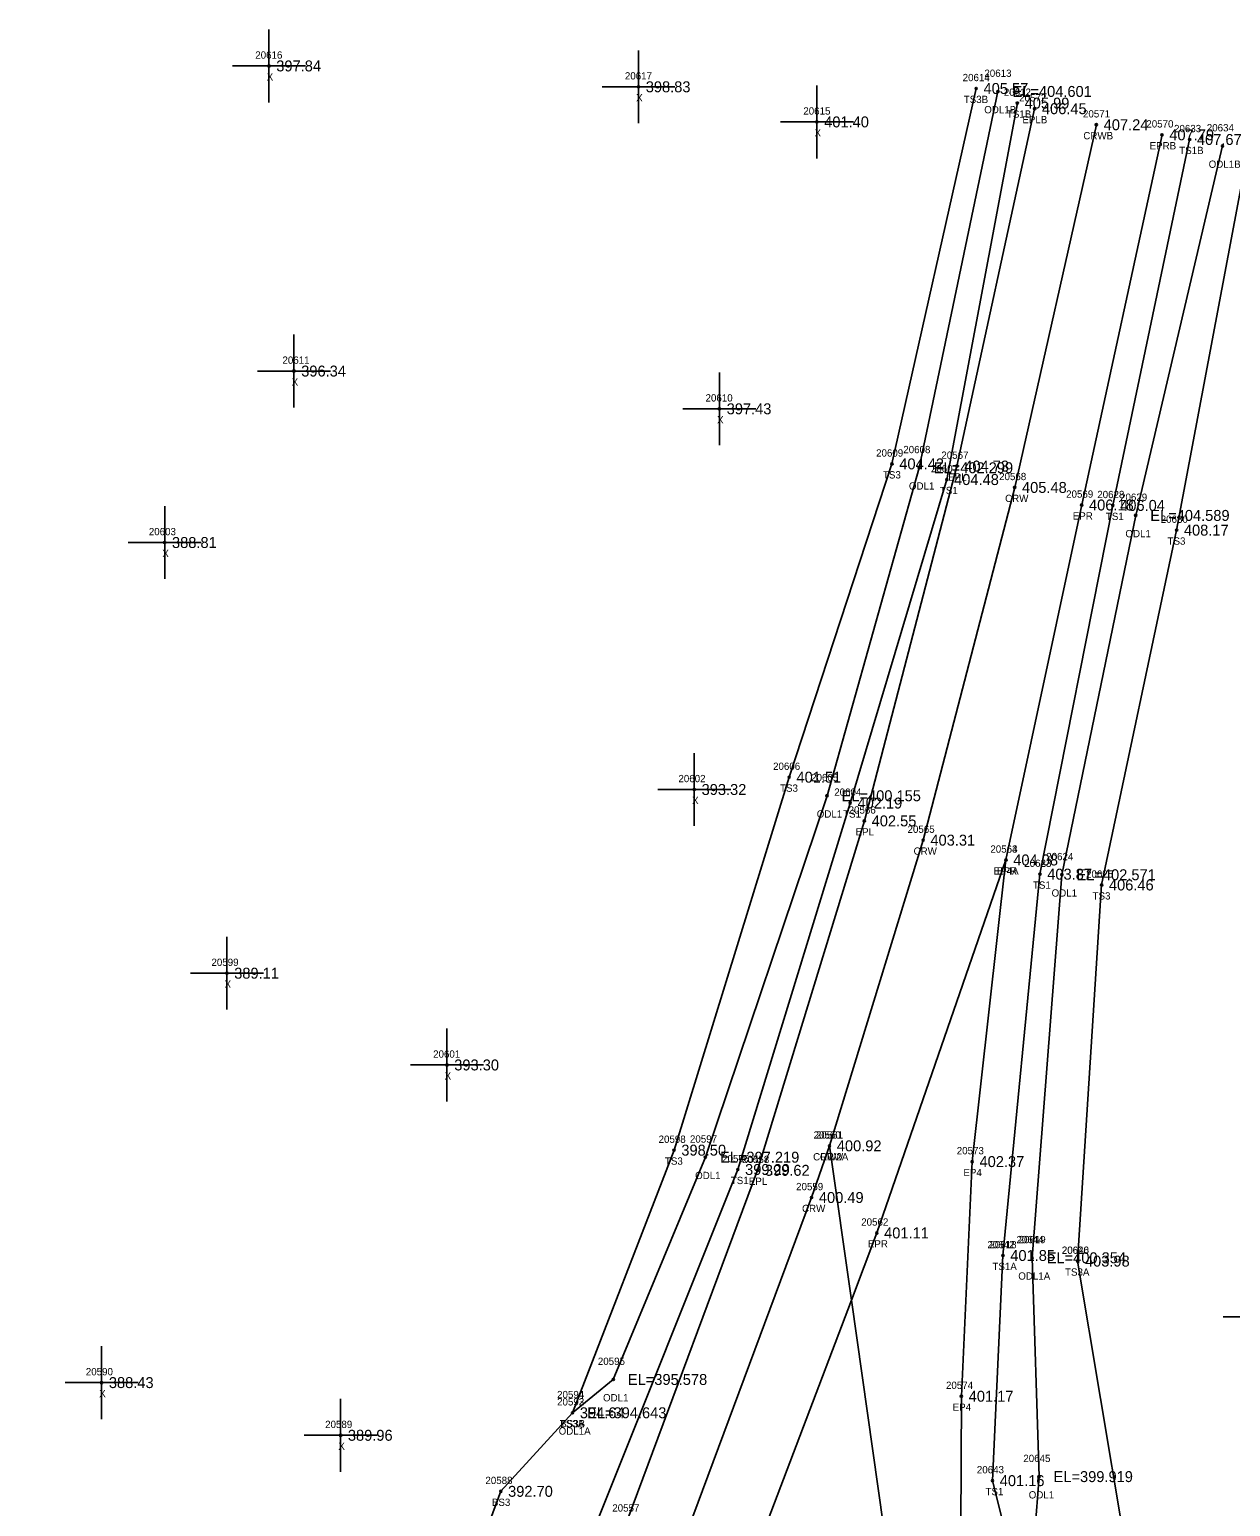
# Model space of a CAD drawing. Extents: x 2116373 to 2118139, y 979529 to 981026.
# Drawn here: x 2117881.7 to 2118046.4, y 980823.7 to 981026.3 of the extents above; entities that cross this region are included whole.
import ezdxf

# ---------------------------------------------------------------- set-up
doc = ezdxf.new("R2010")
doc.units = 0
for name, color, linetype in [('RD_DTM_BkLn1', 7, 'Continuous'), ('RD_DTM_BkLn2', 7, 'Continuous'), ('RD_DTM_BkLn_txCode', 7, 'Continuous'), ('RD_EX_H2O', 7, 'Continuous'), ('RD_EX_H2O_txCode', 7, 'Continuous'), ('RD_EX_Misc', 7, 'Continuous'), ('RD_EX_Misc_txCode', 7, 'Continuous'), ('RD_EX_Road', 7, 'Continuous'), ('RD_EX_Road_txCode', 7, 'Continuous'), ('RD_EX_TX_H2O_ELEV', 7, 'Continuous'), ('RD_EX_TX_Misc_ELEV', 7, 'Continuous'), ('RD_EX_TX_Road_ELEV', 7, 'Continuous'), ('RD_HC_Survey_ELEV', 7, 'Continuous'), ('RD_HC_Survey_txCode', 7, 'Continuous'), ('RD_SMD_Locator', 7, 'Continuous')]:
    doc.layers.add(name, color=color, linetype=linetype)

msp = doc.modelspace()

# ---------------------------------------------------------------- linework, layer by layer
at = {"layer": 'RD_DTM_BkLn1'}
msp.add_line((2117991.42, 980873.14), (2117994.42, 980851.98), dxfattribs=at)
for points in [[(2117394.63, 980185.41), (2117475.35, 980259.39), (2117549.63, 980326.58), (2117623.5, 980394.2), (2117697.55, 980461.75), (2117735.02, 980495.39), (2117805.43, 980566.78), (2117837.53, 980605.36), (2117867.93, 980645.06), (2117897.09, 980686.34), (2117923.66, 980727.51), (2117948.72, 980771.39), (2117971.22, 980818.34), (2117988.96, 980866.05), (2117991.42, 980873.14), (2118004.26, 980915.09), (2118016.82, 980963.49), (2118028.02, 981013.26)], [(2117994.42, 980851.98), (2118001.75, 980800.26), (2118008.52, 980747.72), (2118014.92, 980696.48), (2118020.42, 980643.35)]]:
    msp.add_lwpolyline(points, dxfattribs=at)
at = {"layer": 'RD_DTM_BkLn2'}
for points in [[(2117956.18, 980836.51), (2117970.1, 980872.55), (2117985.89, 980923.73), (2117999.99, 980966.72), (2118011.54, 981018.24)], [(2117493.39, 980317.39), (2117496.3, 980311.64), (2117501.39, 980308.35), (2117540.21, 980337.44), (2117614.76, 980403.8), (2117689.51, 980469.61), (2117729.91, 980504.53), (2117761.86, 980538.86), (2117795.32, 980575.41), (2117828.25, 980612.61), (2117859.59, 980651.69), (2117887.1, 980692.35), (2117913.78, 980733.2), (2117937.24, 980777.08), (2117959.23, 980820.82), (2117978.84, 980869.89), (2117994.26, 980920.18), (2118007.51, 980964.57), (2118017.18, 981016.23)], [(2118015.21, 980858.09), (2118020.28, 980910.42), (2118030.28, 980961.02), (2118040.81, 981011.24)], [(2118025.45, 980857.32), (2118028.74, 980908.94), (2118039.02, 980957.63), (2118048.69, 981009.19)], [(2118015.21, 980858.09), (2118013.77, 980827.2), (2118015.93, 980818.58), (2118019.62, 980749.73), (2118027.82, 980698.51), (2118034.42, 980645.27)], [(2118025.45, 980857.32), (2118031.76, 980819.62), (2118040.05, 980756.49), (2118048.68, 980699.87), (2118049.79, 980645.82)], [(2117731.72, 980517.83), (2117742.59, 980526.71), (2117749.81, 980537.43), (2117757.84, 980543.55), (2117791.08, 980578.67), (2117820.63, 980617.19), (2117852.6, 980656.41), (2117879.28, 980696.02), (2117905.09, 980736.34), (2117929.71, 980780.7), (2117946.34, 980825.73), (2117956.18, 980836.51)]]:
    msp.add_lwpolyline(points, dxfattribs=at)
at = {"layer": 'RD_EX_H2O'}
for points in [[(2117956.18, 980836.51), (2117961.77, 980841.08), (2117974.4, 980871.58), (2117991.08, 980921.18), (2118003.72, 980966.19), (2118014.52, 981017.83)], [(2118019.21, 980857.78), (2118023.29, 980910.34), (2118033.41, 980959.65), (2118045.31, 981010.35)], [(2118019.21, 980857.78), (2118020.15, 980827.75), (2118019.57, 980820.09), (2118020.38, 980817.28), (2118026.54, 980750.63), (2118033.78, 980699.94), (2118041.32, 980645.4)]]:
    msp.add_lwpolyline(points, dxfattribs=at)
at = {"layer": 'RD_EX_Misc'}
for p, q in [((2117914.55, 981016.33), (2117914.55, 981026.33)), ((2117965.22, 981013.47), (2117965.22, 981023.47)), ((2117909.55, 981021.33), (2117919.55, 981021.33)), ((2117960.22, 981018.47), (2117970.22, 981018.47)), ((2117989.69, 981008.65), (2117989.69, 981018.65)), ((2117984.69, 981013.65), (2117994.69, 981013.65)), ((2117917.97, 980974.46), (2117917.97, 980984.46)), ((2117912.97, 980979.46), (2117922.97, 980979.46)), ((2117976.32, 980969.28), (2117976.32, 980979.28)), ((2117971.32, 980974.28), (2117981.32, 980974.28)), ((2117900.25, 980950.93), (2117900.25, 980960.93)), ((2117895.25, 980955.93), (2117905.25, 980955.93)), ((2117972.88, 980917.04), (2117972.88, 980927.04)), ((2117967.88, 980922.04), (2117977.88, 980922.04)), ((2117908.78, 980891.83), (2117908.78, 980901.83)), ((2117903.78, 980896.83), (2117913.78, 980896.83)), ((2117938.96, 980879.24), (2117938.96, 980889.24)), ((2117933.96, 980884.24), (2117943.96, 980884.24)), ((2118045.4, 980849.66), (2118055.4, 980849.66)), ((2117891.59, 980835.65), (2117891.59, 980845.65)), ((2117886.59, 980840.65), (2117896.59, 980840.65)), ((2117924.37, 980828.42), (2117924.37, 980838.42)), ((2117919.37, 980833.42), (2117929.37, 980833.42))]:
    msp.add_line(p, q, dxfattribs=at)
at = {"layer": 'RD_EX_Road'}
for points in [[(2117394.63, 980185.41), (2117388.45, 980192.75), (2117469.76, 980266.25), (2117487.02, 980282.1), (2117515.02, 980307.24), (2117543.53, 980333.04), (2117617.72, 980400.8), (2117691.88, 980468.07), (2117729.57, 980501.96), (2117798.93, 980572.83), (2117831.02, 980611), (2117861.69, 980650.07), (2117890.37, 980690.61), (2117916.67, 980731.93), (2117941.38, 980774.84), (2117963.75, 980821.95), (2117981.56, 980869.78), (2117996.2, 980917.73), (2118008.9, 980966.42), (2118019.55, 981015.46)], [(2117994.42, 980851.98), (2117997.91, 980861.19), (2118015.62, 980912.37), (2118026.01, 980961.08), (2118037.02, 981011.88)], [(2118015.62, 980912.37), (2118010.99, 980870.98), (2118009.51, 980838.78), (2118009.44, 980820.82), (2118010.46, 980800.84), (2118017.48, 980748.87), (2118023.45, 980698.14), (2118029.49, 980644.03)], [(2117394.63, 980185.41), (2117401.85, 980177.36), (2117480.62, 980253.04), (2117556.27, 980319.95), (2117629.74, 980387.35), (2117703.2, 980454.29), (2117741.39, 980488.9), (2117777.53, 980523.58), (2117812.39, 980561.12), (2117844.66, 980599.64), (2117874.87, 980639.35), (2117904.78, 980681.4), (2117931.2, 980722.71), (2117957.05, 980767.35), (2117963.67, 980781.11), (2117980.28, 980814.62), (2117994.42, 980851.98)]]:
    msp.add_lwpolyline(points, dxfattribs=at)
at = {"layer": 'RD_SMD_Locator'}
for centre in [(2117914.55, 981021.33), (2117965.22, 981018.47), (2118011.54, 981018.24), (2118014.52, 981017.83), (2118017.18, 981016.23), (2118019.55, 981015.46), (2117989.69, 981013.65), (2118028.02, 981013.26), (2118037.02, 981011.88), (2118040.81, 981011.24), (2118045.31, 981010.35), (2117917.97, 980979.46), (2117976.32, 980974.28), (2117999.99, 980966.72), (2118003.72, 980966.19), (2118008.9, 980966.42), (2118007.51, 980964.57), (2118016.82, 980963.49), (2118026.01, 980961.08), (2118030.28, 980961.02), (2118033.41, 980959.65), (2118039.02, 980957.63), (2117900.25, 980955.93), (2117985.89, 980923.73), (2117972.88, 980922.04), (2117991.08, 980921.18), (2117994.26, 980920.18), (2117996.2, 980917.73), (2118004.26, 980915.09), (2118015.62, 980912.37), (2118015.62, 980912.37), (2118020.28, 980910.42), (2118023.29, 980910.34), (2118028.74, 980908.94), (2117908.78, 980896.83), (2117938.96, 980884.24), (2117970.1, 980872.55), (2117974.4, 980871.58), (2117991.42, 980873.14), (2117991.42, 980873.14), (2117978.84, 980869.89), (2117981.56, 980869.78), (2118010.99, 980870.98), (2117988.96, 980866.05), (2117997.91, 980861.19), (2118015.21, 980858.09), (2118015.21, 980858.09), (2118019.21, 980857.78), (2118019.21, 980857.78), (2118025.45, 980857.32), (2118025.45, 980857.32), (2117961.77, 980841.08), (2117891.59, 980840.65), (2118009.51, 980838.78), (2117956.18, 980836.51), (2117956.18, 980836.51), (2117956.18, 980836.51), (2117924.37, 980833.42), (2118013.77, 980827.2), (2118020.15, 980827.75), (2117946.34, 980825.73)]:
    msp.add_circle(centre, 0.15, dxfattribs=at)

# ---------------------------------------------------------------- texts
at = {"layer": 'RD_DTM_BkLn_txCode'}
for s, p in [('20614', (2118009.68, 981019.24)), ('20612', (2118015.33, 981017.23)), ('TS3B', (2118009.83, 981016.24)), ('TS1B', (2118015.75, 981014.23)), ('20633', (2118038.67, 981012.24)), ('TS1B', (2118039.38, 981009.24)), ('20609', (2117997.81, 980967.72)), ('TS3', (2117998.75, 980964.72)), ('20607', (2118005.33, 980965.57)), ('TS1', (2118006.55, 980962.57)), ('20628', (2118028.14, 980962.02)), ('TS1', (2118029.32, 980959.02)), ('20630', (2118036.84, 980958.63)), ('TS3', (2118037.78, 980955.63)), ('20606', (2117983.68, 980924.73)), ('TS3', (2117984.64, 980921.73)), ('20604', (2117992.07, 980921.18)), ('TS1', (2117993.29, 980918.18)), ('20623', (2118018.13, 980911.42)), ('20625', (2118026.6, 980909.94)), ('TS1', (2118019.32, 980908.42)), ('TS3', (2118027.5, 980906.94)), ('20598', (2117967.98, 980873.55)), ('20596', (2117976.7, 980870.89)), ('TS3', (2117968.85, 980870.55)), ('TS1', (2117977.88, 980867.89)), ('20642', (2118013.07, 980859.09)), ('20618', (2118013.35, 980859.09)), ('20620', (2118023.27, 980858.32)), ('20646', (2118023.29, 980858.32)), ('TS1A', (2118013.76, 980856.09)), ('TS1A', (2118013.76, 980856.09)), ('TS3A', (2118023.72, 980855.32)), ('TS3A', (2118023.72, 980855.32)), ('20592', (2117954.06, 980837.51)), ('20593', (2117954.06, 980837.51)), ('TS3A', (2117954.44, 980834.51)), ('BS3B', (2117954.48, 980834.51)), ('20643', (2118011.63, 980828.2)), ('20588', (2117944.23, 980826.73)), ('TS1', (2118012.81, 980825.2)), ('BS3', (2117945.12, 980823.73))]:
    msp.add_text(s, height=1, dxfattribs=at).set_placement(p)
at = {"layer": 'RD_EX_H2O_txCode'}
for s, p in [('20613', (2118012.66, 981019.83)), ('ODL1B', (2118012.64, 981014.83)), ('20634', (2118043.16, 981012.35)), ('ODL1B', (2118043.42, 981007.35)), ('20608', (2118001.54, 980968.19)), ('ODL1', (2118002.31, 980963.19)), ('20629', (2118031.27, 980961.65)), ('ODL1', (2118032, 980956.65)), ('20605', (2117988.9, 980923.18)), ('ODL1', (2117989.67, 980918.18)), ('20624', (2118021.14, 980912.34)), ('ODL1', (2118021.88, 980907.34)), ('20597', (2117972.28, 980873.58)), ('ODL1', (2117972.99, 980868.58)), ('20644', (2118017.06, 980859.78)), ('20619', (2118017.35, 980859.78)), ('ODL1A', (2118017.31, 980854.78)), ('ODL1A', (2118017.31, 980854.78)), ('20595', (2117959.65, 980843.08)), ('20594', (2117954.06, 980838.51)), ('ODL1', (2117960.36, 980838.08)), ('ODL1A', (2117954.28, 980833.51)), ('20645', (2118018, 980829.75)), ('ODL1', (2118018.74, 980824.75))]:
    msp.add_text(s, height=1, dxfattribs=at).set_placement(p)
at = {"layer": 'RD_EX_Misc_txCode'}
for s, p in [('20616', (2117912.67, 981022.33)), ('X', (2117914.24, 981019.33)), ('20617', (2117963.36, 981019.47)), ('X', (2117964.9, 981016.47)), ('20615', (2117987.83, 981014.65)), ('X', (2117989.37, 981011.65)), ('20611', (2117916.4, 980980.46)), ('X', (2117917.66, 980977.46)), ('20610', (2117974.42, 980975.28)), ('X', (2117976, 980972.28)), ('20603', (2117898.07, 980956.93)), ('X', (2117899.93, 980953.93)), ('20602', (2117970.7, 980923.04)), ('X', (2117972.57, 980920.04)), ('20599', (2117906.66, 980897.83)), ('X', (2117908.46, 980894.83)), ('20601', (2117937.06, 980885.24)), ('X', (2117938.64, 980882.24)), ('20590', (2117889.43, 980841.65)), ('X', (2117891.27, 980838.65)), ('20589', (2117922.25, 980834.42)), ('X', (2117924.06, 980831.42))]:
    msp.add_text(s, height=1, dxfattribs=at).set_placement(p)
at = {"layer": 'RD_EX_Road_txCode'}
for s, p in [('20572', (2118017.43, 981016.46)), ('EPLB', (2118017.87, 981013.46)), ('20570', (2118034.87, 981012.88)), ('EPRB', (2118035.32, 981009.88)), ('20567', (2118006.76, 980967.42)), ('EPL', (2118007.69, 980964.42)), ('20569', (2118023.87, 980962.08)), ('EPR', (2118024.78, 980959.08)), ('20566', (2117994.04, 980918.73)), ('EPL', (2117995, 980915.73)), ('20563', (2118013.48, 980913.37)), ('20564', (2118013.48, 980913.37)), ('EP4A', (2118013.93, 980910.37)), ('EPR', (2118014.39, 980910.37)), ('20558', (2117979.44, 980870.78)), ('20573', (2118008.87, 980871.98)), ('EP4', (2118009.78, 980868.98)), ('EPL', (2117980.35, 980867.78)), ('20562', (2117995.77, 980862.19)), ('EPR', (2117996.68, 980859.19)), ('20574', (2118007.39, 980839.78)), ('EP4', (2118008.31, 980836.78)), ('20557', (2117961.63, 980822.95))]:
    msp.add_text(s, height=1, dxfattribs=at).set_placement(p)
at = {"layer": 'RD_EX_TX_H2O_ELEV'}
for s, p in [('EL=404.601', (2118016.52, 981017.08)), ('EL=402.299', (2118005.72, 980965.44)), ('EL=404.589', (2118035.41, 980958.9)), ('EL=400.155', (2117993.08, 980920.43)), ('EL=402.571', (2118025.29, 980909.59)), ('EL=397.219', (2117976.4, 980870.83)), ('EL=400.354', (2118021.21, 980857.03)), ('EL=400.354', (2118021.21, 980857.03)), ('EL=395.578', (2117963.77, 980840.33)), ('EL=394.643', (2117958.18, 980835.76)), ('EL=399.919', (2118022.15, 980827))]:
    msp.add_text(s, height=1.5, dxfattribs=at).set_placement(p)
at = {"layer": 'RD_EX_TX_Misc_ELEV'}
for s, p in [('397.84', (2117915.55, 981020.58)), ('398.83', (2117966.22, 981017.72)), ('405.57', (2118012.54, 981017.49)), ('405.99', (2118018.18, 981015.48)), ('401.40', (2117990.69, 981012.9)), ('407.67', (2118041.81, 981010.49)), ('396.34', (2117918.97, 980978.71)), ('397.43', (2117977.32, 980973.53)), ('404.42', (2118000.99, 980965.97)), ('404.48', (2118008.51, 980963.82)), ('406.04', (2118031.28, 980960.27)), ('408.17', (2118040.02, 980956.88)), ('388.81', (2117901.25, 980955.18)), ('401.51', (2117986.89, 980922.98)), ('393.32', (2117973.88, 980921.29)), ('402.19', (2117995.26, 980919.43)), ('403.87', (2118021.28, 980909.67)), ('406.46', (2118029.74, 980908.19)), ('389.11', (2117909.78, 980896.08)), ('393.30', (2117939.96, 980883.49)), ('398.50', (2117971.1, 980871.8)), ('399.29', (2117979.84, 980869.14)), ('401.85', (2118016.21, 980857.34)), ('401.85', (2118016.21, 980857.34)), ('403.98', (2118026.45, 980856.57)), ('403.98', (2118026.45, 980856.57)), ('388.43', (2117892.59, 980839.9)), ('394.64', (2117957.18, 980835.76)), ('394.64', (2117957.18, 980835.76)), ('389.96', (2117925.37, 980832.67)), ('401.16', (2118014.77, 980826.45)), ('392.70', (2117947.34, 980824.98))]:
    msp.add_text(s, height=1.5, dxfattribs=at).set_placement(p)
at = {"layer": 'RD_EX_TX_Road_ELEV'}
for s, p in [('406.45', (2118020.55, 981014.71)), ('407.79', (2118038.02, 981011.13)), ('404.73', (2118009.9, 980965.67)), ('406.18', (2118027.01, 980960.33)), ('402.55', (2117997.2, 980916.98)), ('404.08', (2118016.62, 980911.62)), ('404.08', (2118016.62, 980911.62)), ('402.37', (2118011.99, 980870.23)), ('399.62', (2117982.56, 980869.03)), ('401.11', (2117998.91, 980860.44)), ('401.17', (2118010.51, 980838.03))]:
    msp.add_text(s, height=1.5, dxfattribs=at).set_placement(p)
at = {"layer": 'RD_HC_Survey_ELEV'}
for s, p in [('407.24', (2118029.02, 981012.51)), ('405.48', (2118017.82, 980962.74)), ('403.31', (2118005.26, 980914.34)), ('400.92', (2117992.42, 980872.39)), ('400.92', (2117992.42, 980872.39)), ('400.49', (2117989.96, 980865.3))]:
    msp.add_text(s, height=1.5, dxfattribs=at).set_placement(p)
at = {"layer": 'RD_HC_Survey_txCode'}
for s, p in [('20571', (2118026.18, 981014.26)), ('CRWB', (2118026.23, 981011.26)), ('20568', (2118014.68, 980964.49)), ('CRW', (2118015.5, 980961.49)), ('20565', (2118002.12, 980916.09)), ('CRW', (2118002.95, 980913.09)), ('20560', (2117989.24, 980874.14)), ('20561', (2117989.56, 980874.14)), ('CRW2A', (2117989.17, 980871.14)), ('CRW', (2117990.1, 980871.14)), ('20559', (2117986.84, 980867.05)), ('CRW', (2117987.65, 980864.05))]:
    msp.add_text(s, height=1, dxfattribs=at).set_placement(p)

doc.saveas('drawing.dxf')
